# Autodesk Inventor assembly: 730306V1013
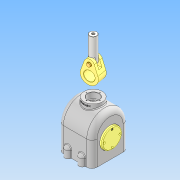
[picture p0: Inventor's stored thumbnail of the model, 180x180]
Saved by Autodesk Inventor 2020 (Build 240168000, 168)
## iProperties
Created: 2023-03
Part Number: 730306V1013
Document SubType Name: Assembly
Designer: user
Author: user
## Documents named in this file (10)
- C:\Users\user\Desktop\730306V1013\730306V1013.iam
- C:\Users\user\Desktop\730306V1013\본체.ipt
- C:\Users\user\Desktop\730306V1013\고정핀.ipt
- C:\Users\user\Desktop\730306V1013\링크.ipt
- C:\Users\user\Desktop\730306V1013\슬라이더.ipt
- C:\Users\user\Desktop\730306V1013\편심축.ipt
- C:\Users\user\Desktop\730306V1013\베어링 6205.ipt
- 베어링 6205.ipt
- C:\Users\user\Desktop\730306V1013\뒷커버.ipt
- C:\Users\user\Desktop\730306V1013\볼트 M4 x 12.ipt
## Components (1 placed, 1 different names)
1. 고정핀:1
